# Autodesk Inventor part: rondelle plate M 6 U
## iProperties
Author: chr
Created: 2001-06
Part Number: rondelle plate M 6 U
Material: Par défaut
Document SubType Name: Modélisation
Designer: chr
Control State: 0
Master: False
Checked Out: False
PropertySet Name: Design Tracking Control
Shininess: 20.0
PropertySet Name: _Private Model Information
Length Units: 11269
Angle Units: 11286
Time Units: 11279
Mass Units: 11290
Length Display Precision: 3
Angle Display Precision: 2
Compacted: False
Density: 0.0
Volumn: 0.0
Area: 0.0
PropertySet Name: Model Information
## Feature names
1. Base1
